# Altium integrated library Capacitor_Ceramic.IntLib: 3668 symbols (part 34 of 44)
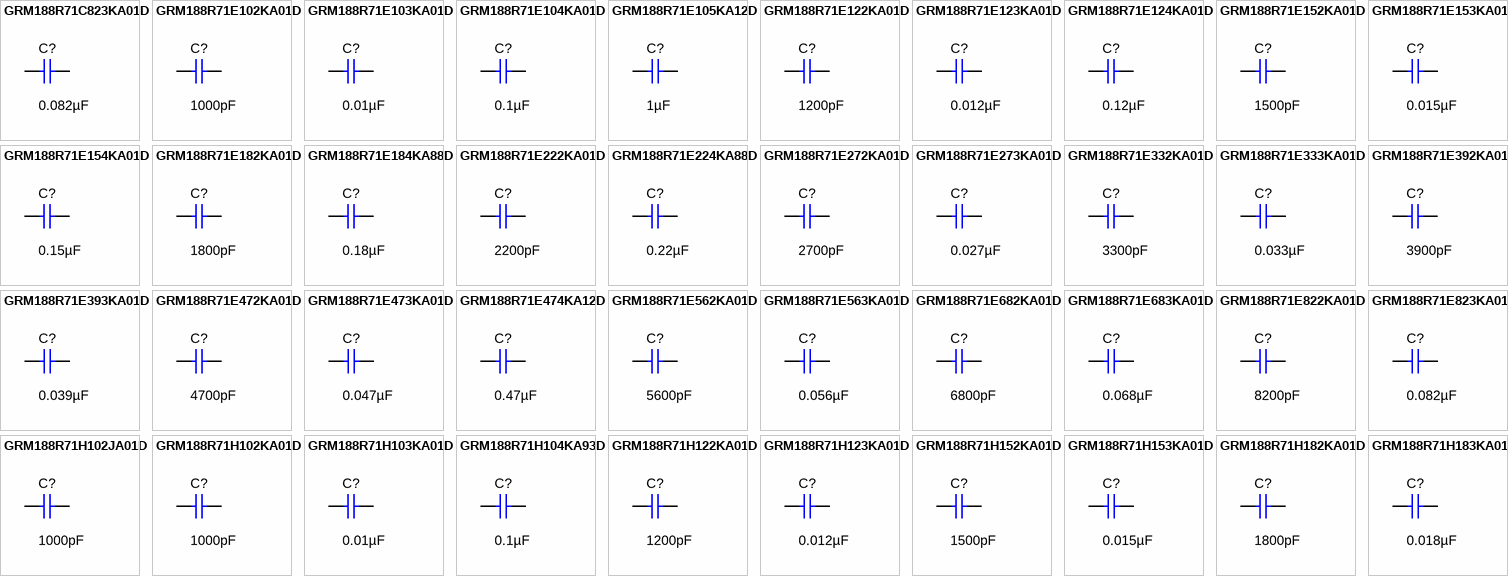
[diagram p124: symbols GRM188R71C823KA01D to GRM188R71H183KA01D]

## GRM188R71E123KA01D
designator C?  ValueDisplayed: 0.012µF  (hidden comment: GRM188R71E123KA01D)
CAP, CERM, 0.012 µF, 25 V,+/- 10%, X7R, 0603; Manufacturer: MuRata; Polarized: N; CompType: Capacitor; Value: 0.012uF; U/M: EA; Cap_F: 0.000000012; Tolerance_%: 10; VDC_V: 25; Value2: 25V; TaMin_C: -55; TaMax_C: 125; Cap_Case: 0603; SizeArea_mm2: 1.28; SizeAreaWB_mm2: 4.68; SizeX_mm: 1.6; SizeY_mm: 0.8; SizeZ_mm: 1; AEC Category: Q200
signal-integrity model Cap
simulation model Cap
footprint 0603
footprint 0603M
footprint 0603L
footprint 0603_HV
footprint 0603S
pins: 1, 2

## GRM188R71E124KA01D
designator C?  ValueDisplayed: 0.12µF  (hidden comment: GRM188R71E124KA01D)
CAP, CERM, 0.12 µF, 25 V,+/- 10%, X7R, 0603; Manufacturer: MuRata; Polarized: N; CompType: Capacitor; Value: 0.12uF; U/M: EA; Cap_F: 0.00000012; Tolerance_%: 10; VDC_V: 25; Value2: 25V; TaMin_C: -55; TaMax_C: 125; Cap_Case: 0603; SizeArea_mm2: 1.28; SizeAreaWB_mm2: 4.68; SizeX_mm: 1.6; SizeY_mm: 0.8; SizeZ_mm: 1; AEC Category: Q200
signal-integrity model Cap
simulation model Cap
footprint 0603
footprint 0603M
footprint 0603L
footprint 0603_HV
footprint 0603S
pins: 1, 2

## GRM188R71E152KA01D
designator C?  ValueDisplayed: 1500pF  (hidden comment: GRM188R71E152KA01D)
CAP, CERM, 1500 pF, 25 V,+/- 10%, X7R, 0603; Manufacturer: MuRata; Polarized: N; CompType: Capacitor; Value: 1500pF; U/M: EA; Cap_F: 0.0000000015; Tolerance_%: 10; VDC_V: 25; Value2: 25V; TaMin_C: -55; TaMax_C: 125; Cap_Case: 0603; SizeArea_mm2: 1.28; SizeAreaWB_mm2: 4.68; SizeX_mm: 1.6; SizeY_mm: 0.8; SizeZ_mm: 1; AEC Category: Q200; Green_Lifecycle: Active; Green_REACh: Passed
signal-integrity model Cap
simulation model Cap
footprint 0603
footprint 0603M
footprint 0603L
footprint 0603_HV
footprint 0603S
pins: 1, 2

## GRM188R71E153KA01D
designator C?  ValueDisplayed: 0.015µF  (hidden comment: GRM188R71E153KA01D)
CAP, CERM, 0.015 µF, 25 V,+/- 10%, X7R, 0603; Manufacturer: MuRata; Polarized: N; CompType: Capacitor; Value: 0.015uF; U/M: EA; Cap_F: 0.000000015; Tolerance_%: 10; VDC_V: 25; Value2: 25V; TaMin_C: -55; TaMax_C: 125; Cap_Case: 0603; SizeArea_mm2: 1.28; SizeAreaWB_mm2: 4.68; SizeX_mm: 1.6; SizeY_mm: 0.8; SizeZ_mm: 1; AEC Category: Q200; Green_Lifecycle: Active; Green_REACh: Passed
signal-integrity model Cap
simulation model Cap
footprint 0603
footprint 0603M
footprint 0603L
footprint 0603_HV
footprint 0603S
pins: 1, 2

## GRM188R71E154KA01D
designator C?  ValueDisplayed: 0.15µF  (hidden comment: GRM188R71E154KA01D)
CAP, CERM, 0.15 µF, 25 V,+/- 10%, X7R, 0603; Manufacturer: MuRata; Polarized: N; CompType: Capacitor; Value: 0.15uF; U/M: EA; Cap_F: 0.00000015; Tolerance_%: 10; VDC_V: 25; Value2: 25V; TaMin_C: -55; TaMax_C: 125; Cap_Case: 0603; SizeArea_mm2: 1.28; SizeAreaWB_mm2: 4.68; SizeX_mm: 1.6; SizeY_mm: 0.8; SizeZ_mm: 1; AEC Category: Q200; Green_Lifecycle: Active; Green_REACh: Passed
signal-integrity model Cap
simulation model Cap
footprint 0603
footprint 0603M
footprint 0603L
footprint 0603_HV
footprint 0603S
pins: 1, 2

## GRM188R71E182KA01D
designator C?  ValueDisplayed: 1800pF  (hidden comment: GRM188R71E182KA01D)
CAP, CERM, 1800 pF, 25 V,+/- 10%, X7R, 0603; Manufacturer: MuRata; Polarized: N; CompType: Capacitor; Value: 1800pF; U/M: EA; Cap_F: 0.0000000018; Tolerance_%: 10; VDC_V: 25; Value2: 25V; TaMin_C: -55; TaMax_C: 125; Cap_Case: 0603; SizeArea_mm2: 1.28; SizeAreaWB_mm2: 4.68; SizeX_mm: 1.6; SizeY_mm: 0.8; SizeZ_mm: 1; AEC Category: Q200; Green_Lifecycle: Active; Green_REACh: Passed
signal-integrity model Cap
simulation model Cap
footprint 0603
footprint 0603M
footprint 0603L
footprint 0603_HV
footprint 0603S
pins: 1, 2

## GRM188R71E184KA88D
designator C?  ValueDisplayed: 0.18µF  (hidden comment: GRM188R71E184KA88D)
CAP, CERM, 0.18 µF, 25 V,+/- 10%, X7R, 0603; Manufacturer: MuRata; Polarized: N; CompType: Capacitor; Value: 0.18uF; U/M: EA; Cap_F: 0.00000018; Tolerance_%: 10; VDC_V: 25; Value2: 25V; TaMin_C: -55; TaMax_C: 125; Cap_Case: 0603; SizeArea_mm2: 1.28; SizeAreaWB_mm2: 4.68; SizeX_mm: 1.6; SizeY_mm: 0.8; SizeZ_mm: 1; AEC Category: Q200; Green_Lifecycle: Active; Green_REACh: Passed
signal-integrity model Cap
simulation model Cap
footprint 0603
footprint 0603M
footprint 0603L
footprint 0603_HV
footprint 0603S
pins: 1, 2

## GRM188R71E222KA01D
designator C?  ValueDisplayed: 2200pF  (hidden comment: GRM188R71E222KA01D)
CAP, CERM, 2200 pF, 25 V,+/- 10%, X7R, 0603; Manufacturer: MuRata; Polarized: N; CompType: Capacitor; Value: 2200pF; U/M: EA; Cap_F: 0.0000000022; Tolerance_%: 10; VDC_V: 25; Value2: 25V; TaMin_C: -55; TaMax_C: 125; Cap_Case: 0603; SizeArea_mm2: 1.28; SizeAreaWB_mm2: 4.68; SizeX_mm: 1.6; SizeY_mm: 0.8; SizeZ_mm: 1; AEC Category: Q200; Green_Lifecycle: Active; Green_REACh: Passed
signal-integrity model Cap
simulation model Cap
footprint 0603
footprint 0603M
footprint 0603L
footprint 0603_HV
footprint 0603S
pins: 1, 2

## GRM188R71E224KA88D
designator C?  ValueDisplayed: 0.22µF  (hidden comment: GRM188R71E224KA88D)
CAP, CERM, 0.22 µF, 25 V,+/- 10%, X7R, 0603; Manufacturer: MuRata; Polarized: N; CompType: Capacitor; Value: 0.22uF; U/M: EA; Cap_F: 0.00000022; Tolerance_%: 10; VDC_V: 25; Value2: 25V; TaMin_C: -55; TaMax_C: 125; Cap_Case: 0603; SizeArea_mm2: 1.28; SizeAreaWB_mm2: 4.68; SizeX_mm: 1.6; SizeY_mm: 0.8; SizeZ_mm: 1; AEC Category: Q200; Green_Lifecycle: Active; Green_REACh: Passed
signal-integrity model Cap
simulation model Cap
footprint 0603
footprint 0603M
footprint 0603L
footprint 0603_HV
footprint 0603S
pins: 1, 2

## GRM188R71E272KA01D
designator C?  ValueDisplayed: 2700pF  (hidden comment: GRM188R71E272KA01D)
CAP, CERM, 2700 pF, 25 V,+/- 10%, X7R, 0603; Manufacturer: MuRata; Polarized: N; CompType: Capacitor; Value: 2700pF; U/M: EA; Cap_F: 0.0000000027; Tolerance_%: 10; VDC_V: 25; Value2: 25V; TaMin_C: -55; TaMax_C: 125; Cap_Case: 0603; SizeArea_mm2: 1.28; SizeAreaWB_mm2: 4.68; SizeX_mm: 1.6; SizeY_mm: 0.8; SizeZ_mm: 1; AEC Category: Q200; Green_Lifecycle: Active; Green_REACh: Passed
signal-integrity model Cap
simulation model Cap
footprint 0603
footprint 0603M
footprint 0603L
footprint 0603_HV
footprint 0603S
pins: 1, 2

## GRM188R71E273KA01D
designator C?  ValueDisplayed: 0.027µF  (hidden comment: GRM188R71E273KA01D)
CAP, CERM, 0.027 µF, 25 V,+/- 10%, X7R, 0603; Manufacturer: MuRata; Polarized: N; CompType: Capacitor; Value: 0.027uF; U/M: EA; Cap_F: 0.000000027; Tolerance_%: 10; VDC_V: 25; Value2: 25V; TaMin_C: -55; TaMax_C: 125; Cap_Case: 0603; SizeArea_mm2: 1.28; SizeAreaWB_mm2: 4.68; SizeX_mm: 1.6; SizeY_mm: 0.8; SizeZ_mm: 1; AEC Category: Q200
signal-integrity model Cap
simulation model Cap
footprint 0603
footprint 0603M
footprint 0603L
footprint 0603_HV
footprint 0603S
pins: 1, 2

## GRM188R71E332KA01D
designator C?  ValueDisplayed: 3300pF  (hidden comment: GRM188R71E332KA01D)
CAP, CERM, 3300 pF, 25 V,+/- 10%, X7R, 0603; Manufacturer: MuRata; Polarized: N; CompType: Capacitor; Value: 3300pF; U/M: EA; Cap_F: 0.0000000033; Tolerance_%: 10; VDC_V: 25; Value2: 25V; TaMin_C: -55; TaMax_C: 125; Cap_Case: 0603; SizeArea_mm2: 1.28; SizeAreaWB_mm2: 4.68; SizeX_mm: 1.6; SizeY_mm: 0.8; SizeZ_mm: 1; AEC Category: Q200; Green_Lifecycle: Active; Green_REACh: Passed
signal-integrity model Cap
simulation model Cap
footprint 0603
footprint 0603M
footprint 0603L
footprint 0603_HV
footprint 0603S
pins: 1, 2

## GRM188R71E333KA01D
designator C?  ValueDisplayed: 0.033µF  (hidden comment: GRM188R71E333KA01D)
CAP, CERM, 0.033 µF, 25 V,+/- 10%, X7R, 0603; Manufacturer: MuRata; Polarized: N; CompType: Capacitor; Value: 0.033uF; U/M: EA; Cap_F: 0.000000033; Tolerance_%: 10; VDC_V: 25; Value2: 25V; TaMin_C: -55; TaMax_C: 125; Cap_Case: 0603; SizeArea_mm2: 1.28; SizeAreaWB_mm2: 4.68; SizeX_mm: 1.6; SizeY_mm: 0.8; SizeZ_mm: 1; AEC Category: Q200; Green_Lifecycle: Active; Green_REACh: Passed
signal-integrity model Cap
simulation model Cap
footprint 0603
footprint 0603M
footprint 0603L
footprint 0603_HV
footprint 0603S
pins: 1, 2

## GRM188R71E392KA01D
designator C?  ValueDisplayed: 3900pF  (hidden comment: GRM188R71E392KA01D)
CAP, CERM, 3900 pF, 25 V,+/- 10%, X7R, 0603; Manufacturer: MuRata; Polarized: N; CompType: Capacitor; Value: 3900pF; U/M: EA; Cap_F: 0.0000000039; Tolerance_%: 10; VDC_V: 25; Value2: 25V; TaMin_C: -55; TaMax_C: 125; Cap_Case: 0603; SizeArea_mm2: 1.28; SizeAreaWB_mm2: 4.68; SizeX_mm: 1.6; SizeY_mm: 0.8; SizeZ_mm: 1; AEC Category: Q200; Green_Lifecycle: Active; Green_REACh: Passed
signal-integrity model Cap
simulation model Cap
footprint 0603
footprint 0603M
footprint 0603L
footprint 0603_HV
footprint 0603S
pins: 1, 2

## GRM188R71E393KA01D
designator C?  ValueDisplayed: 0.039µF  (hidden comment: GRM188R71E393KA01D)
CAP, CERM, 0.039 µF, 25 V,+/- 10%, X7R, 0603; Manufacturer: MuRata; Polarized: N; CompType: Capacitor; Value: 0.039uF; U/M: EA; Cap_F: 0.000000039; Tolerance_%: 10; VDC_V: 25; Value2: 25V; TaMin_C: -55; TaMax_C: 125; Cap_Case: 0603; SizeArea_mm2: 1.28; SizeAreaWB_mm2: 4.68; SizeX_mm: 1.6; SizeY_mm: 0.8; SizeZ_mm: 1; AEC Category: Q200
signal-integrity model Cap
simulation model Cap
footprint 0603
footprint 0603M
footprint 0603L
footprint 0603_HV
footprint 0603S
pins: 1, 2

## GRM188R71E472KA01D
designator C?  ValueDisplayed: 4700pF  (hidden comment: GRM188R71E472KA01D)
CAP, CERM, 4700 pF, 25 V,+/- 10%, X7R, 0603; Manufacturer: MuRata; Polarized: N; CompType: Capacitor; Value: 4700pF; U/M: EA; Cap_F: 0.0000000047; Tolerance_%: 10; VDC_V: 25; Value2: 25V; TaMin_C: -55; TaMax_C: 125; Cap_Case: 0603; SizeArea_mm2: 1.28; SizeAreaWB_mm2: 4.68; SizeX_mm: 1.6; SizeY_mm: 0.8; SizeZ_mm: 1; AEC Category: Q200
signal-integrity model Cap
simulation model Cap
footprint 0603
footprint 0603M
footprint 0603L
footprint 0603_HV
footprint 0603S
pins: 1, 2

## GRM188R71E473KA01D
designator C?  ValueDisplayed: 0.047µF  (hidden comment: GRM188R71E473KA01D)
CAP, CERM, 0.047 µF, 25 V,+/- 10%, X7R, 0603; Manufacturer: MuRata; Polarized: N; CompType: Capacitor; Value: 0.047uF; U/M: EA; Cap_F: 0.000000047; Tolerance_%: 10; VDC_V: 25; Value2: 25V; TaMin_C: -55; TaMax_C: 125; Cap_Case: 0603; SizeArea_mm2: 1.28; SizeAreaWB_mm2: 4.68; SizeX_mm: 1.6; SizeY_mm: 0.8; SizeZ_mm: 1; AEC Category: Q200; Green_Lifecycle: Active; Green_REACh: Passed
signal-integrity model Cap
simulation model Cap
footprint 0603
footprint 0603M
footprint 0603L
footprint 0603_HV
footprint 0603S
pins: 1, 2

## GRM188R71E474KA12D
designator C?  ValueDisplayed: 0.47µF  (hidden comment: GRM188R71E474KA12D)
CAP, CERM, 0.47 µF, 25 V,+/- 10%, X7R, 0603; Manufacturer: MuRata; Polarized: N; CompType: Capacitor; Value: 0.47uF; U/M: EA; Cap_F: 0.00000047; Tolerance_%: 10; VDC_V: 25; Value2: 25V; TaMin_C: -55; TaMax_C: 125; Cap_Case: 0603; SizeArea_mm2: 1.28; SizeAreaWB_mm2: 4.68; SizeX_mm: 1.6; SizeY_mm: 0.8; SizeZ_mm: 1; AEC Category: Q200; Green_Lifecycle: Active; Green_REACh: Passed
signal-integrity model Cap
simulation model Cap
footprint 0603
footprint 0603M
footprint 0603L
footprint 0603_HV
footprint 0603S
pins: 1, 2

## GRM188R71E562KA01D
designator C?  ValueDisplayed: 5600pF  (hidden comment: GRM188R71E562KA01D)
CAP, CERM, 5600 pF, 25 V,+/- 10%, X7R, 0603; Manufacturer: MuRata; Polarized: N; CompType: Capacitor; Value: 5600pF; U/M: EA; Cap_F: 0.0000000056; Tolerance_%: 10; VDC_V: 25; Value2: 25V; TaMin_C: -55; TaMax_C: 125; Cap_Case: 0603; SizeArea_mm2: 1.28; SizeAreaWB_mm2: 4.68; SizeX_mm: 1.6; SizeY_mm: 0.8; SizeZ_mm: 1; AEC Category: Q200
signal-integrity model Cap
simulation model Cap
footprint 0603
footprint 0603M
footprint 0603L
footprint 0603_HV
footprint 0603S
pins: 1, 2

## GRM188R71E563KA01D
designator C?  ValueDisplayed: 0.056µF  (hidden comment: GRM188R71E563KA01D)
CAP, CERM, 0.056 µF, 25 V,+/- 10%, X7R, 0603; Manufacturer: MuRata; Polarized: N; CompType: Capacitor; Value: 0.056uF; U/M: EA; Cap_F: 0.000000056; Tolerance_%: 10; VDC_V: 25; Value2: 25V; TaMin_C: -55; TaMax_C: 125; Cap_Case: 0603; SizeArea_mm2: 1.28; SizeAreaWB_mm2: 4.68; SizeX_mm: 1.6; SizeY_mm: 0.8; SizeZ_mm: 1; AEC Category: Q200; Green_Lifecycle: Active; Green_REACh: Passed
signal-integrity model Cap
simulation model Cap
footprint 0603
footprint 0603M
footprint 0603L
footprint 0603_HV
footprint 0603S
pins: 1, 2

## GRM188R71E682KA01D
designator C?  ValueDisplayed: 6800pF  (hidden comment: GRM188R71E682KA01D)
CAP, CERM, 6800 pF, 25 V,+/- 10%, X7R, 0603; Manufacturer: MuRata; Polarized: N; CompType: Capacitor; Value: 6800pF; U/M: EA; Cap_F: 0.0000000068; Tolerance_%: 10; VDC_V: 25; Value2: 25V; TaMin_C: -55; TaMax_C: 125; Cap_Case: 0603; SizeArea_mm2: 1.28; SizeAreaWB_mm2: 4.68; SizeX_mm: 1.6; SizeY_mm: 0.8; SizeZ_mm: 1; AEC Category: Q200
signal-integrity model Cap
simulation model Cap
footprint 0603
footprint 0603M
footprint 0603L
footprint 0603_HV
footprint 0603S
pins: 1, 2

## GRM188R71E683KA01D
designator C?  ValueDisplayed: 0.068µF  (hidden comment: GRM188R71E683KA01D)
CAP, CERM, 0.068 µF, 25 V,+/- 10%, X7R, 0603; Manufacturer: MuRata; Polarized: N; CompType: Capacitor; Value: 0.068uF; U/M: EA; Cap_F: 0.000000068; Tolerance_%: 10; VDC_V: 25; Value2: 25V; TaMin_C: -55; TaMax_C: 125; Cap_Case: 0603; SizeArea_mm2: 1.28; SizeAreaWB_mm2: 4.68; SizeX_mm: 1.6; SizeY_mm: 0.8; SizeZ_mm: 1; AEC Category: Q200; Green_Lifecycle: Active; Green_REACh: Passed
signal-integrity model Cap
simulation model Cap
footprint 0603
footprint 0603M
footprint 0603L
footprint 0603_HV
footprint 0603S
pins: 1, 2

## GRM188R71E822KA01D
designator C?  ValueDisplayed: 8200pF  (hidden comment: GRM188R71E822KA01D)
CAP, CERM, 8200 pF, 25 V,+/- 10%, X7R, 0603; Manufacturer: MuRata; Polarized: N; CompType: Capacitor; Value: 8200pF; U/M: EA; Cap_F: 0.0000000082; Tolerance_%: 10; VDC_V: 25; Value2: 25V; TaMin_C: -55; TaMax_C: 125; Cap_Case: 0603; SizeArea_mm2: 1.28; SizeAreaWB_mm2: 4.68; SizeX_mm: 1.6; SizeY_mm: 0.8; SizeZ_mm: 1; AEC Category: Q200; Green_Lifecycle: Active; Green_REACh: Passed
signal-integrity model Cap
simulation model Cap
footprint 0603
footprint 0603M
footprint 0603L
footprint 0603_HV
footprint 0603S
pins: 1, 2

## GRM188R71E823KA01D
designator C?  ValueDisplayed: 0.082µF  (hidden comment: GRM188R71E823KA01D)
CAP, CERM, 0.082 µF, 25 V,+/- 10%, X7R, 0603; Manufacturer: MuRata; Polarized: N; CompType: Capacitor; Value: 0.082uF; U/M: EA; Cap_F: 0.000000082; Tolerance_%: 10; VDC_V: 25; Value2: 25V; TaMin_C: -55; TaMax_C: 125; Cap_Case: 0603; SizeArea_mm2: 1.28; SizeAreaWB_mm2: 4.68; SizeX_mm: 1.6; SizeY_mm: 0.8; SizeZ_mm: 1; AEC Category: Q200; Green_Lifecycle: Active; Green_REACh: Passed
signal-integrity model Cap
simulation model Cap
footprint 0603
footprint 0603M
footprint 0603L
footprint 0603_HV
footprint 0603S
pins: 1, 2

## GRM188R71H102JA01D
designator C?  ValueDisplayed: 1000pF  (hidden comment: GRM188R71H102JA01D)
CAP, CERM, 1000 pF, 50 V,+/- 5%, X7R, 0603; Manufacturer: MuRata; Polarized: N; CompType: Capacitor; Value: 1000pF; U/M: EA; Cap_F: 0.000000001; Tolerance_%: 5; VDC_V: 50; Value2: 50V; TaMin_C: -55; TaMax_C: 125; Cap_Case: 0603; SizeArea_mm2: 1.28; SizeAreaWB_mm2: 4.68; SizeX_mm: 1.6; SizeY_mm: 0.8; SizeZ_mm: 1; AEC Category: Q200
signal-integrity model Cap
simulation model Cap
footprint 0603
footprint 0603M
footprint 0603L
footprint 0603_HV
footprint 0603S
pins: 1, 2

## GRM188R71H102KA01D
designator C?  ValueDisplayed: 1000pF  (hidden comment: GRM188R71H102KA01D)
CAP, CERM, 1000 pF, 50 V,+/- 10%, X7R, 0603; Manufacturer: MuRata; Polarized: N; CompType: Capacitor; Value: 1000pF; U/M: EA; Cap_F: 0.000000001; Tolerance_%: 10; VDC_V: 50; Value2: 50V; TaMin_C: -55; TaMax_C: 125; Cap_Case: 0603; SizeArea_mm2: 1.28; SizeAreaWB_mm2: 4.68; SizeX_mm: 1.6; SizeY_mm: 0.8; SizeZ_mm: 1; AEC Category: Q200; Green_Lifecycle: Active; Green_REACh: Passed
signal-integrity model Cap
simulation model Cap
footprint 0603
footprint 0603M
footprint 0603L
footprint 0603_HV
footprint 0603S
pins: 1, 2

## GRM188R71H103KA01D
designator C?  ValueDisplayed: 0.01µF  (hidden comment: GRM188R71H103KA01D)
CAP, CERM, 0.01 µF, 50 V,+/- 10%, X7R, 0603; Manufacturer: MuRata; Polarized: N; CompType: Capacitor; Value: 0.01uF; U/M: EA; Cap_F: 0.00000001; Tolerance_%: 10; VDC_V: 50; Value2: 50V; TaMin_C: -55; TaMax_C: 125; Cap_Case: 0603; SizeArea_mm2: 1.28; SizeAreaWB_mm2: 4.68; SizeX_mm: 1.6; SizeY_mm: 0.8; SizeZ_mm: 1; AEC Category: Q200; Green_Lifecycle: Active; Green_REACh: Passed
signal-integrity model Cap
simulation model Cap
footprint 0603
footprint 0603M
footprint 0603L
footprint 0603_HV
footprint 0603S
pins: 1, 2

## GRM188R71H104KA93D
designator C?  ValueDisplayed: 0.1µF  (hidden comment: GRM188R71H104KA93D)
CAP, CERM, 0.1 µF, 50 V,+/- 10%, X7R, 0603; Manufacturer: MuRata; Polarized: N; CompType: Capacitor; Value: 0.1uF; U/M: EA; Cap_F: 0.0000001; Tolerance_%: 10; VDC_V: 50; Value2: 50V; TaMin_C: -55; TaMax_C: 125; Cap_Case: 0603; SizeArea_mm2: 1.28; SizeAreaWB_mm2: 4.68; SizeX_mm: 1.6; SizeY_mm: 0.8; SizeZ_mm: 1; AEC Category: Q200; Green_Lifecycle: Active; Green_REACh: Passed
signal-integrity model Cap
simulation model Cap
footprint 0603
footprint 0603M
footprint 0603L
footprint 0603_HV
footprint 0603S
pins: 1, 2

## GRM188R71H122KA01D
designator C?  ValueDisplayed: 1200pF  (hidden comment: GRM188R71H122KA01D)
CAP, CERM, 1200 pF, 50 V,+/- 10%, X7R, 0603; Manufacturer: MuRata; Polarized: N; CompType: Capacitor; Value: 1200pF; U/M: EA; Cap_F: 0.0000000012; Tolerance_%: 10; VDC_V: 50; Value2: 50V; TaMin_C: -55; TaMax_C: 125; Cap_Case: 0603; SizeArea_mm2: 1.28; SizeAreaWB_mm2: 4.68; SizeX_mm: 1.6; SizeY_mm: 0.8; SizeZ_mm: 1; AEC Category: Q200; Green_Lifecycle: Active; Green_REACh: Passed
signal-integrity model Cap
simulation model Cap
footprint 0603
footprint 0603M
footprint 0603L
footprint 0603_HV
footprint 0603S
pins: 1, 2

## GRM188R71H123KA01D
designator C?  ValueDisplayed: 0.012µF  (hidden comment: GRM188R71H123KA01D)
CAP, CERM, 0.012 µF, 50 V,+/- 10%, X7R, 0603; Manufacturer: MuRata; Polarized: N; CompType: Capacitor; Value: 0.012uF; U/M: EA; Cap_F: 0.000000012; Tolerance_%: 10; VDC_V: 50; Value2: 50V; TaMin_C: -55; TaMax_C: 125; Cap_Case: 0603; SizeArea_mm2: 1.28; SizeAreaWB_mm2: 4.68; SizeX_mm: 1.6; SizeY_mm: 0.8; SizeZ_mm: 1; AEC Category: Q200; Green_Lifecycle: Active; Green_REACh: Passed
signal-integrity model Cap
simulation model Cap
footprint 0603
footprint 0603M
footprint 0603L
footprint 0603_HV
footprint 0603S
pins: 1, 2

## GRM188R71H152KA01D
designator C?  ValueDisplayed: 1500pF  (hidden comment: GRM188R71H152KA01D)
CAP, CERM, 1500 pF, 50 V,+/- 10%, X7R, 0603; Manufacturer: MuRata; Polarized: N; CompType: Capacitor; Value: 1500pF; U/M: EA; Cap_F: 0.0000000015; Tolerance_%: 10; VDC_V: 50; Value2: 50V; TaMin_C: -55; TaMax_C: 125; Cap_Case: 0603; SizeArea_mm2: 1.28; SizeAreaWB_mm2: 4.68; SizeX_mm: 1.6; SizeY_mm: 0.8; SizeZ_mm: 1; AEC Category: Q200; Green_Lifecycle: Active; Green_REACh: Passed
signal-integrity model Cap
simulation model Cap
footprint 0603
footprint 0603M
footprint 0603L
footprint 0603_HV
footprint 0603S
pins: 1, 2

## GRM188R71H153KA01D
designator C?  ValueDisplayed: 0.015µF  (hidden comment: GRM188R71H153KA01D)
CAP, CERM, 0.015 µF, 50 V,+/- 10%, X7R, 0603; Manufacturer: MuRata; Polarized: N; CompType: Capacitor; Value: 0.015uF; U/M: EA; Cap_F: 0.000000015; Tolerance_%: 10; VDC_V: 50; Value2: 50V; TaMin_C: -55; TaMax_C: 125; Cap_Case: 0603; SizeArea_mm2: 1.28; SizeAreaWB_mm2: 4.68; SizeX_mm: 1.6; SizeY_mm: 0.8; SizeZ_mm: 1; AEC Category: Q200; Green_Lifecycle: Active; Green_REACh: Passed
signal-integrity model Cap
simulation model Cap
footprint 0603
footprint 0603M
footprint 0603L
footprint 0603_HV
footprint 0603S
pins: 1, 2

## GRM188R71H182KA01D
designator C?  ValueDisplayed: 1800pF  (hidden comment: GRM188R71H182KA01D)
CAP, CERM, 1800 pF, 50 V,+/- 10%, X7R, 0603; Manufacturer: MuRata; Polarized: N; CompType: Capacitor; Value: 1800pF; U/M: EA; Cap_F: 0.0000000018; Tolerance_%: 10; VDC_V: 50; Value2: 50V; TaMin_C: -55; TaMax_C: 125; Cap_Case: 0603; SizeArea_mm2: 1.28; SizeAreaWB_mm2: 4.68; SizeX_mm: 1.6; SizeY_mm: 0.8; SizeZ_mm: 1; AEC Category: Q200; Green_Lifecycle: Active; Green_REACh: Passed
signal-integrity model Cap
simulation model Cap
footprint 0603
footprint 0603M
footprint 0603L
footprint 0603_HV
footprint 0603S
pins: 1, 2

## GRM188R71H183KA01D
designator C?  ValueDisplayed: 0.018µF  (hidden comment: GRM188R71H183KA01D)
CAP, CERM, 0.018 µF, 50 V,+/- 10%, X7R, 0603; Manufacturer: MuRata; Polarized: N; CompType: Capacitor; Value: 0.018uF; U/M: EA; Cap_F: 0.000000018; Tolerance_%: 10; VDC_V: 50; Value2: 50V; TaMin_C: -55; TaMax_C: 125; Cap_Case: 0603; SizeArea_mm2: 1.28; SizeAreaWB_mm2: 4.68; SizeX_mm: 1.6; SizeY_mm: 0.8; SizeZ_mm: 1; AEC Category: Q200
signal-integrity model Cap
simulation model Cap
footprint 0603
footprint 0603M
footprint 0603L
footprint 0603_HV
footprint 0603S
pins: 1, 2

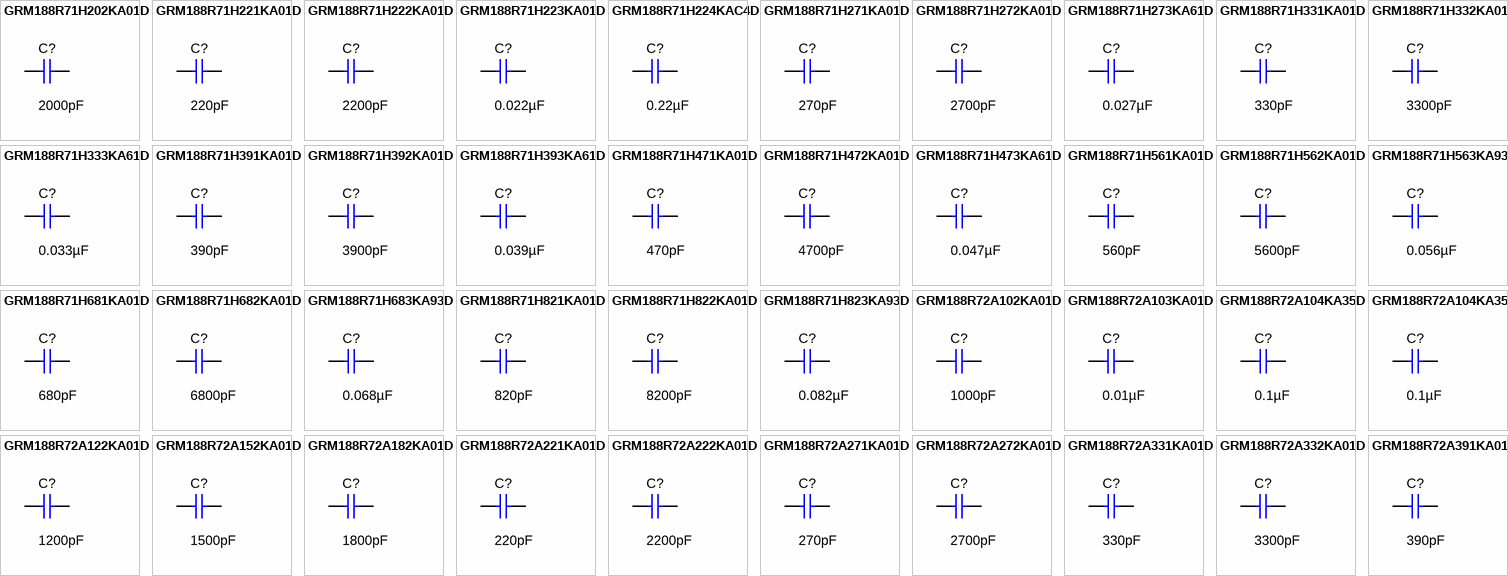
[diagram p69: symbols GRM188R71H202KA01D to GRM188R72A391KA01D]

## GRM188R71H202KA01D
designator C?  ValueDisplayed: 2000pF  (hidden comment: GRM188R71H202KA01D)
CAP, CERM, 2000 pF, 50 V,+/- 10%, X7R, 0603; Manufacturer: MuRata; Polarized: N; CompType: Capacitor; Value: 2000pF; U/M: EA; Cap_F: 0.000000002; Tolerance_%: 10; VDC_V: 50; Value2: 50V; TaMin_C: -55; TaMax_C: 125; Cap_Case: 0603; SizeArea_mm2: 1.28; SizeAreaWB_mm2: 4.68; SizeX_mm: 1.6; SizeY_mm: 0.8; SizeZ_mm: 1; AEC Category: Q200
signal-integrity model Cap
simulation model Cap
footprint 0603
footprint 0603M
footprint 0603L
footprint 0603_HV
footprint 0603S
pins: 1, 2

## GRM188R71H221KA01D
designator C?  ValueDisplayed: 220pF  (hidden comment: GRM188R71H221KA01D)
CAP, CERM, 220 pF, 50 V,+/- 10%, X7R, 0603; Manufacturer: MuRata; Polarized: N; CompType: Capacitor; Value: 220pF; U/M: EA; Cap_F: 0.00000000022; Tolerance_%: 10; VDC_V: 50; Value2: 50V; TaMin_C: -55; TaMax_C: 125; Cap_Case: 0603; SizeArea_mm2: 1.28; SizeAreaWB_mm2: 4.68; SizeX_mm: 1.6; SizeY_mm: 0.8; SizeZ_mm: 1; AEC Category: Q200; Green_Lifecycle: Active; Green_REACh: Passed
signal-integrity model Cap
simulation model Cap
footprint 0603
footprint 0603M
footprint 0603L
footprint 0603_HV
footprint 0603S
pins: 1, 2

## GRM188R71H222KA01D
designator C?  ValueDisplayed: 2200pF  (hidden comment: GRM188R71H222KA01D)
CAP, CERM, 2200 pF, 50 V,+/- 10%, X7R, 0603; Manufacturer: MuRata; Polarized: N; CompType: Capacitor; Value: 2200pF; U/M: EA; Cap_F: 0.0000000022; Tolerance_%: 10; VDC_V: 50; Value2: 50V; TaMin_C: -55; TaMax_C: 125; Cap_Case: 0603; SizeArea_mm2: 1.28; SizeAreaWB_mm2: 4.68; SizeX_mm: 1.6; SizeY_mm: 0.8; SizeZ_mm: 1; AEC Category: Q200; Green_Lifecycle: Active; Green_REACh: Passed
signal-integrity model Cap
simulation model Cap
footprint 0603
footprint 0603M
footprint 0603L
footprint 0603_HV
footprint 0603S
pins: 1, 2

## GRM188R71H223KA01D
designator C?  ValueDisplayed: 0.022µF  (hidden comment: GRM188R71H223KA01D)
CAP, CERM, 0.022 µF, 50 V,+/- 10%, X7R, 0603; Manufacturer: MuRata; Polarized: N; CompType: Capacitor; Value: 0.022uF; U/M: EA; Cap_F: 0.000000022; Tolerance_%: 10; VDC_V: 50; Value2: 50V; TaMin_C: -55; TaMax_C: 125; Cap_Case: 0603; SizeArea_mm2: 1.28; SizeAreaWB_mm2: 4.68; SizeX_mm: 1.6; SizeY_mm: 0.8; SizeZ_mm: 1; AEC Category: Q200; Green_Lifecycle: Active; Green_REACh: Passed
signal-integrity model Cap
simulation model Cap
footprint 0603
footprint 0603M
footprint 0603L
footprint 0603_HV
footprint 0603S
pins: 1, 2

## GRM188R71H224KAC4D
designator C?  ValueDisplayed: 0.22µF  (hidden comment: GRM188R71H224KAC4D)
CAP, CERM, 0.22 µF, 50 V,+/- 10%, X7R, 0603; Manufacturer: MuRata; Polarized: N; CompType: Capacitor; Value: 0.22uF; U/M: EA; Cap_F: 0.00000022; Tolerance_%: 10; VDC_V: 50; Value2: 50V; TaMin_C: -55; TaMax_C: 125; Cap_Case: 0603; SizeArea_mm2: 1.28; SizeAreaWB_mm2: 4.68; SizeX_mm: 1.6; SizeY_mm: 0.8; SizeZ_mm: 1; AEC Category: Q200
signal-integrity model Cap
simulation model Cap
footprint 0603
footprint 0603M
footprint 0603L
footprint 0603_HV
footprint 0603S
pins: 1, 2

## GRM188R71H271KA01D
designator C?  ValueDisplayed: 270pF  (hidden comment: GRM188R71H271KA01D)
CAP, CERM, 270 pF, 50 V,+/- 10%, X7R, 0603; Manufacturer: MuRata; Polarized: N; CompType: Capacitor; Value: 270pF; U/M: EA; Cap_F: 0.00000000027; Tolerance_%: 10; VDC_V: 50; Value2: 50V; TaMin_C: -55; TaMax_C: 125; Cap_Case: 0603; SizeArea_mm2: 1.28; SizeAreaWB_mm2: 4.68; SizeX_mm: 1.6; SizeY_mm: 0.8; SizeZ_mm: 1; AEC Category: Q200
signal-integrity model Cap
simulation model Cap
footprint 0603
footprint 0603M
footprint 0603L
footprint 0603_HV
footprint 0603S
pins: 1, 2

## GRM188R71H272KA01D
designator C?  ValueDisplayed: 2700pF  (hidden comment: GRM188R71H272KA01D)
CAP, CERM, 2700 pF, 50 V,+/- 10%, X7R, 0603; Manufacturer: MuRata; Polarized: N; CompType: Capacitor; Value: 2700pF; U/M: EA; Cap_F: 0.0000000027; Tolerance_%: 10; VDC_V: 50; Value2: 50V; TaMin_C: -55; TaMax_C: 125; Cap_Case: 0603; SizeArea_mm2: 1.28; SizeAreaWB_mm2: 4.68; SizeX_mm: 1.6; SizeY_mm: 0.8; SizeZ_mm: 1; AEC Category: Q200; Green_Lifecycle: Active; Green_REACh: Passed
signal-integrity model Cap
simulation model Cap
footprint 0603
footprint 0603M
footprint 0603L
footprint 0603_HV
footprint 0603S
pins: 1, 2

## GRM188R71H273KA61D
designator C?  ValueDisplayed: 0.027µF  (hidden comment: GRM188R71H273KA61D)
CAP, CERM, 0.027 µF, 50 V,+/- 10%, X7R, 0603; Manufacturer: MuRata; Polarized: N; CompType: Capacitor; Value: 0.027uF; U/M: EA; Cap_F: 0.000000027; Tolerance_%: 10; VDC_V: 50; Value2: 50V; TaMin_C: -55; TaMax_C: 125; Cap_Case: 0603; SizeArea_mm2: 1.28; SizeAreaWB_mm2: 4.68; SizeX_mm: 1.6; SizeY_mm: 0.8; SizeZ_mm: 1; AEC Category: Q200
signal-integrity model Cap
simulation model Cap
footprint 0603
footprint 0603M
footprint 0603L
footprint 0603_HV
footprint 0603S
pins: 1, 2

## GRM188R71H331KA01D
designator C?  ValueDisplayed: 330pF  (hidden comment: GRM188R71H331KA01D)
CAP, CERM, 330 pF, 50 V,+/- 10%, X7R, 0603; Manufacturer: MuRata; Polarized: N; CompType: Capacitor; Value: 330pF; U/M: EA; Cap_F: 0.00000000033; Tolerance_%: 10; VDC_V: 50; Value2: 50V; TaMin_C: -55; TaMax_C: 125; Cap_Case: 0603; SizeArea_mm2: 1.28; SizeAreaWB_mm2: 4.68; SizeX_mm: 1.6; SizeY_mm: 0.8; SizeZ_mm: 1; AEC Category: Q200; Green_Lifecycle: Active; Green_REACh: Passed
signal-integrity model Cap
simulation model Cap
footprint 0603
footprint 0603M
footprint 0603L
footprint 0603_HV
footprint 0603S
pins: 1, 2

## GRM188R71H332KA01D
designator C?  ValueDisplayed: 3300pF  (hidden comment: GRM188R71H332KA01D)
CAP, CERM, 3300 pF, 50 V,+/- 10%, X7R, 0603; Manufacturer: MuRata; Polarized: N; CompType: Capacitor; Value: 3300pF; U/M: EA; Cap_F: 0.0000000033; Tolerance_%: 10; VDC_V: 50; Value2: 50V; TaMin_C: -55; TaMax_C: 125; Cap_Case: 0603; SizeArea_mm2: 1.28; SizeAreaWB_mm2: 4.68; SizeX_mm: 1.6; SizeY_mm: 0.8; SizeZ_mm: 1; AEC Category: Q200; Green_Lifecycle: Active; Green_REACh: Passed
signal-integrity model Cap
simulation model Cap
footprint 0603
footprint 0603M
footprint 0603L
footprint 0603_HV
footprint 0603S
pins: 1, 2

## GRM188R71H333KA61D
designator C?  ValueDisplayed: 0.033µF  (hidden comment: GRM188R71H333KA61D)
CAP, CERM, 0.033 µF, 50 V,+/- 10%, X7R, 0603; Manufacturer: MuRata; Polarized: N; CompType: Capacitor; Value: 0.033uF; U/M: EA; Cap_F: 0.000000033; Tolerance_%: 10; VDC_V: 50; Value2: 50V; TaMin_C: -55; TaMax_C: 125; Cap_Case: 0603; SizeArea_mm2: 1.28; SizeAreaWB_mm2: 4.68; SizeX_mm: 1.6; SizeY_mm: 0.8; SizeZ_mm: 1; AEC Category: Q200; Green_Lifecycle: Active; Green_REACh: Passed
signal-integrity model Cap
simulation model Cap
footprint 0603
footprint 0603M
footprint 0603L
footprint 0603_HV
footprint 0603S
pins: 1, 2

## GRM188R71H391KA01D
designator C?  ValueDisplayed: 390pF  (hidden comment: GRM188R71H391KA01D)
CAP, CERM, 390 pF, 50 V,+/- 10%, X7R, 0603; Manufacturer: MuRata; Polarized: N; CompType: Capacitor; Value: 390pF; U/M: EA; Cap_F: 0.00000000039; Tolerance_%: 10; VDC_V: 50; Value2: 50V; TaMin_C: -55; TaMax_C: 125; Cap_Case: 0603; SizeArea_mm2: 1.28; SizeAreaWB_mm2: 4.68; SizeX_mm: 1.6; SizeY_mm: 0.8; SizeZ_mm: 1; AEC Category: Q200
signal-integrity model Cap
simulation model Cap
footprint 0603
footprint 0603M
footprint 0603L
footprint 0603_HV
footprint 0603S
pins: 1, 2

## GRM188R71H392KA01D
designator C?  ValueDisplayed: 3900pF  (hidden comment: GRM188R71H392KA01D)
CAP, CERM, 3900 pF, 50 V,+/- 10%, X7R, 0603; Manufacturer: MuRata; Polarized: N; CompType: Capacitor; Value: 3900pF; U/M: EA; Cap_F: 0.0000000039; Tolerance_%: 10; VDC_V: 50; Value2: 50V; TaMin_C: -55; TaMax_C: 125; Cap_Case: 0603; SizeArea_mm2: 1.28; SizeAreaWB_mm2: 4.68; SizeX_mm: 1.6; SizeY_mm: 0.8; SizeZ_mm: 1; AEC Category: Q200; Green_Lifecycle: Active; Green_REACh: Passed
signal-integrity model Cap
simulation model Cap
footprint 0603
footprint 0603M
footprint 0603L
footprint 0603_HV
footprint 0603S
pins: 1, 2

## GRM188R71H393KA61D
designator C?  ValueDisplayed: 0.039µF  (hidden comment: GRM188R71H393KA61D)
CAP, CERM, 0.039 µF, 50 V,+/- 10%, X7R, 0603; Manufacturer: MuRata; Polarized: N; CompType: Capacitor; Value: 0.039uF; U/M: EA; Cap_F: 0.000000039; Tolerance_%: 10; VDC_V: 50; Value2: 50V; TaMin_C: -55; TaMax_C: 125; Cap_Case: 0603; SizeArea_mm2: 1.28; SizeAreaWB_mm2: 4.68; SizeX_mm: 1.6; SizeY_mm: 0.8; SizeZ_mm: 1; AEC Category: Q200
signal-integrity model Cap
simulation model Cap
footprint 0603
footprint 0603M
footprint 0603L
footprint 0603_HV
footprint 0603S
pins: 1, 2

## GRM188R71H471KA01D
designator C?  ValueDisplayed: 470pF  (hidden comment: GRM188R71H471KA01D)
CAP, CERM, 470 pF, 50 V,+/- 10%, X7R, 0603; Manufacturer: MuRata; Polarized: N; CompType: Capacitor; Value: 470pF; U/M: EA; Cap_F: 0.00000000047; Tolerance_%: 10; VDC_V: 50; Value2: 50V; TaMin_C: -55; TaMax_C: 125; Cap_Case: 0603; SizeArea_mm2: 1.28; SizeAreaWB_mm2: 4.68; SizeX_mm: 1.6; SizeY_mm: 0.8; SizeZ_mm: 1; AEC Category: Q200; Green_Lifecycle: Active; Green_REACh: Passed
signal-integrity model Cap
simulation model Cap
footprint 0603
footprint 0603M
footprint 0603L
footprint 0603_HV
footprint 0603S
pins: 1, 2

## GRM188R71H472KA01D
designator C?  ValueDisplayed: 4700pF  (hidden comment: GRM188R71H472KA01D)
CAP, CERM, 4700 pF, 50 V,+/- 10%, X7R, 0603; Manufacturer: MuRata; Polarized: N; CompType: Capacitor; Value: 4700pF; U/M: EA; Cap_F: 0.0000000047; Tolerance_%: 10; VDC_V: 50; Value2: 50V; TaMin_C: -55; TaMax_C: 125; Cap_Case: 0603; SizeArea_mm2: 1.28; SizeAreaWB_mm2: 4.68; SizeX_mm: 1.6; SizeY_mm: 0.8; SizeZ_mm: 1; AEC Category: Q200; Green_Lifecycle: Active; Green_REACh: Passed
signal-integrity model Cap
simulation model Cap
footprint 0603
footprint 0603M
footprint 0603L
footprint 0603_HV
footprint 0603S
pins: 1, 2

## GRM188R71H473KA61D
designator C?  ValueDisplayed: 0.047µF  (hidden comment: GRM188R71H473KA61D)
CAP, CERM, 0.047 µF, 50 V,+/- 10%, X7R, 0603; Manufacturer: MuRata; Polarized: N; CompType: Capacitor; Value: 0.047uF; U/M: EA; Cap_F: 0.000000047; Tolerance_%: 10; VDC_V: 50; Value2: 50V; TaMin_C: -55; TaMax_C: 125; Cap_Case: 0603; SizeArea_mm2: 1.28; SizeAreaWB_mm2: 4.68; SizeX_mm: 1.6; SizeY_mm: 0.8; SizeZ_mm: 1; AEC Category: Q200; Green_Lifecycle: Active; Green_REACh: Passed
signal-integrity model Cap
simulation model Cap
footprint 0603
footprint 0603M
footprint 0603L
footprint 0603_HV
footprint 0603S
pins: 1, 2

## GRM188R71H561KA01D
designator C?  ValueDisplayed: 560pF  (hidden comment: GRM188R71H561KA01D)
CAP, CERM, 560 pF, 50 V,+/- 10%, X7R, 0603; Manufacturer: MuRata; Polarized: N; CompType: Capacitor; Value: 560pF; U/M: EA; Cap_F: 0.00000000056; Tolerance_%: 10; VDC_V: 50; Value2: 50V; TaMin_C: -55; TaMax_C: 125; Cap_Case: 0603; SizeArea_mm2: 1.28; SizeAreaWB_mm2: 4.68; SizeX_mm: 1.6; SizeY_mm: 0.8; SizeZ_mm: 1; AEC Category: Q200
signal-integrity model Cap
simulation model Cap
footprint 0603
footprint 0603M
footprint 0603L
footprint 0603_HV
footprint 0603S
pins: 1, 2

## GRM188R71H562KA01D
designator C?  ValueDisplayed: 5600pF  (hidden comment: GRM188R71H562KA01D)
CAP, CERM, 5600 pF, 50 V,+/- 10%, X7R, 0603; Manufacturer: MuRata; Polarized: N; CompType: Capacitor; Value: 5600pF; U/M: EA; Cap_F: 0.0000000056; Tolerance_%: 10; VDC_V: 50; Value2: 50V; TaMin_C: -55; TaMax_C: 125; Cap_Case: 0603; SizeArea_mm2: 1.28; SizeAreaWB_mm2: 4.68; SizeX_mm: 1.6; SizeY_mm: 0.8; SizeZ_mm: 1; AEC Category: Q200; Green_Lifecycle: Active; Green_REACh: Passed
signal-integrity model Cap
simulation model Cap
footprint 0603
footprint 0603M
footprint 0603L
footprint 0603_HV
footprint 0603S
pins: 1, 2

## GRM188R71H563KA93D
designator C?  ValueDisplayed: 0.056µF  (hidden comment: GRM188R71H563KA93D)
CAP, CERM, 0.056 µF, 50 V,+/- 10%, X7R, 0603; Manufacturer: MuRata; Polarized: N; CompType: Capacitor; Value: 0.056uF; U/M: EA; Cap_F: 0.000000056; Tolerance_%: 10; VDC_V: 50; Value2: 50V; TaMin_C: -55; TaMax_C: 125; Cap_Case: 0603; SizeArea_mm2: 1.28; SizeAreaWB_mm2: 4.68; SizeX_mm: 1.6; SizeY_mm: 0.8; SizeZ_mm: 1; AEC Category: Q200; Green_Lifecycle: Active; Green_REACh: Passed
signal-integrity model Cap
simulation model Cap
footprint 0603
footprint 0603M
footprint 0603L
footprint 0603_HV
footprint 0603S
pins: 1, 2

## GRM188R71H681KA01D
designator C?  ValueDisplayed: 680pF  (hidden comment: GRM188R71H681KA01D)
CAP, CERM, 680 pF, 50 V,+/- 10%, X7R, 0603; Manufacturer: MuRata; Polarized: N; CompType: Capacitor; Value: 680pF; U/M: EA; Cap_F: 0.00000000068; Tolerance_%: 10; VDC_V: 50; Value2: 50V; TaMin_C: -55; TaMax_C: 125; Cap_Case: 0603; SizeArea_mm2: 1.28; SizeAreaWB_mm2: 4.68; SizeX_mm: 1.6; SizeY_mm: 0.8; SizeZ_mm: 1; AEC Category: Q200; Green_Lifecycle: Active; Green_REACh: Passed
signal-integrity model Cap
simulation model Cap
footprint 0603
footprint 0603M
footprint 0603L
footprint 0603_HV
footprint 0603S
pins: 1, 2

## GRM188R71H682KA01D
designator C?  ValueDisplayed: 6800pF  (hidden comment: GRM188R71H682KA01D)
CAP, CERM, 6800 pF, 50 V,+/- 10%, X7R, 0603; Manufacturer: MuRata; Polarized: N; CompType: Capacitor; Value: 6800pF; U/M: EA; Cap_F: 0.0000000068; Tolerance_%: 10; VDC_V: 50; Value2: 50V; TaMin_C: -55; TaMax_C: 125; Cap_Case: 0603; SizeArea_mm2: 1.28; SizeAreaWB_mm2: 4.68; SizeX_mm: 1.6; SizeY_mm: 0.8; SizeZ_mm: 1; AEC Category: Q200; Green_Lifecycle: Active; Green_REACh: Passed
signal-integrity model Cap
simulation model Cap
footprint 0603
footprint 0603M
footprint 0603L
footprint 0603_HV
footprint 0603S
pins: 1, 2

## GRM188R71H683KA93D
designator C?  ValueDisplayed: 0.068µF  (hidden comment: GRM188R71H683KA93D)
CAP, CERM, 0.068 µF, 50 V,+/- 10%, X7R, 0603; Manufacturer: MuRata; Polarized: N; CompType: Capacitor; Value: 0.068uF; U/M: EA; Cap_F: 0.000000068; Tolerance_%: 10; VDC_V: 50; Value2: 50V; TaMin_C: -55; TaMax_C: 125; Cap_Case: 0603; SizeArea_mm2: 1.28; SizeAreaWB_mm2: 4.68; SizeX_mm: 1.6; SizeY_mm: 0.8; SizeZ_mm: 1; AEC Category: Q200; Green_Lifecycle: Active; Green_REACh: Passed
signal-integrity model Cap
simulation model Cap
footprint 0603
footprint 0603M
footprint 0603L
footprint 0603_HV
footprint 0603S
pins: 1, 2

## GRM188R71H821KA01D
designator C?  ValueDisplayed: 820pF  (hidden comment: GRM188R71H821KA01D)
CAP, CERM, 820 pF, 50 V,+/- 10%, X7R, 0603; Manufacturer: MuRata; Polarized: N; CompType: Capacitor; Value: 820pF; U/M: EA; Cap_F: 0.00000000082; Tolerance_%: 10; VDC_V: 50; Value2: 50V; TaMin_C: -55; TaMax_C: 125; Cap_Case: 0603; SizeArea_mm2: 1.28; SizeAreaWB_mm2: 4.68; SizeX_mm: 1.6; SizeY_mm: 0.8; SizeZ_mm: 1; AEC Category: Q200; Green_Lifecycle: Active; Green_REACh: Passed
signal-integrity model Cap
simulation model Cap
footprint 0603
footprint 0603M
footprint 0603L
footprint 0603_HV
footprint 0603S
pins: 1, 2

## GRM188R71H822KA01D
designator C?  ValueDisplayed: 8200pF  (hidden comment: GRM188R71H822KA01D)
CAP, CERM, 8200 pF, 50 V,+/- 10%, X7R, 0603; Manufacturer: MuRata; Polarized: N; CompType: Capacitor; Value: 8200pF; U/M: EA; Cap_F: 0.0000000082; Tolerance_%: 10; VDC_V: 50; Value2: 50V; TaMin_C: -55; TaMax_C: 125; Cap_Case: 0603; SizeArea_mm2: 1.28; SizeAreaWB_mm2: 4.68; SizeX_mm: 1.6; SizeY_mm: 0.8; SizeZ_mm: 1; AEC Category: Q200; Green_Lifecycle: Active; Green_REACh: Passed
signal-integrity model Cap
simulation model Cap
footprint 0603
footprint 0603M
footprint 0603L
footprint 0603_HV
footprint 0603S
pins: 1, 2

## GRM188R71H823KA93D
designator C?  ValueDisplayed: 0.082µF  (hidden comment: GRM188R71H823KA93D)
CAP, CERM, 0.082 µF, 50 V,+/- 10%, X7R, 0603; Manufacturer: MuRata; Polarized: N; CompType: Capacitor; Value: 0.082uF; U/M: EA; Cap_F: 0.000000082; Tolerance_%: 10; VDC_V: 50; Value2: 50V; TaMin_C: -55; TaMax_C: 125; Cap_Case: 0603; SizeArea_mm2: 1.28; SizeAreaWB_mm2: 4.68; SizeX_mm: 1.6; SizeY_mm: 0.8; SizeZ_mm: 1; AEC Category: Q200; Green_Lifecycle: Active; Green_REACh: Passed
signal-integrity model Cap
simulation model Cap
footprint 0603
footprint 0603M
footprint 0603L
footprint 0603_HV
footprint 0603S
pins: 1, 2

## GRM188R72A102KA01D
designator C?  ValueDisplayed: 1000pF  (hidden comment: GRM188R72A102KA01D)
CAP, CERM, 1000 pF, 100 V,+/- 10%, X7R, 0603; Manufacturer: MuRata; Polarized: N; CompType: Capacitor; Value: 1000pF; U/M: EA; Cap_F: 0.000000001; Tolerance_%: 10; VDC_V: 100; Value2: 100V; TaMin_C: -55; TaMax_C: 125; Cap_Case: 0603; SizeArea_mm2: 1.28; SizeAreaWB_mm2: 4.68; SizeX_mm: 1.6; SizeY_mm: 0.8; SizeZ_mm: 1; AEC Category: Q200; Green_Lifecycle: Active; Green_REACh: Passed
signal-integrity model Cap
simulation model Cap
footprint 0603
footprint 0603M
footprint 0603L
footprint 0603_HV
footprint 0603S
pins: 1, 2

## GRM188R72A103KA01D
designator C?  ValueDisplayed: 0.01µF  (hidden comment: GRM188R72A103KA01D)
CAP, CERM, 0.01 µF, 100 V,+/- 10%, X7R, 0603; Manufacturer: MuRata; Polarized: N; CompType: Capacitor; Value: 0.01uF; U/M: EA; Cap_F: 0.00000001; Tolerance_%: 10; VDC_V: 100; Value2: 100V; TaMin_C: -55; TaMax_C: 125; Cap_Case: 0603; SizeArea_mm2: 1.28; SizeAreaWB_mm2: 4.68; SizeX_mm: 1.6; SizeY_mm: 0.8; SizeZ_mm: 1; AEC Category: Q200; Green_Lifecycle: Active; Green_REACh: Passed
signal-integrity model Cap
simulation model Cap
footprint 0603
footprint 0603M
footprint 0603L
footprint 0603_HV
footprint 0603S
pins: 1, 2

## GRM188R72A104KA35D
designator C?  ValueDisplayed: 0.1µF  (hidden comment: GRM188R72A104KA35D)
CAP, CERM, 0.1 µF, 100 V,+/- 10%, X7R, 0603; Manufacturer: MuRata; Polarized: N; CompType: Capacitor; Value: 0.1uF; U/M: EA; Cap_F: 0.0000001; Tolerance_%: 10; VDC_V: 100; Value2: 100V; TaMin_C: -55; TaMax_C: 125; Cap_Case: 0603; SizeArea_mm2: 1.28; SizeAreaWB_mm2: 4.68; SizeX_mm: 1.6; SizeY_mm: 0.8; SizeZ_mm: 1; AEC Category: Q200; Green_Lifecycle: Active; Green_REACh: Passed
signal-integrity model Cap
simulation model Cap
footprint 0603
footprint 0603M
footprint 0603L
footprint 0603_HV
footprint 0603S
pins: 1, 2

## GRM188R72A104KA35J
designator C?  ValueDisplayed: 0.1µF  (hidden comment: GRM188R72A104KA35J)
CAP, CERM, 0.1 µF, 100 V,+/- 10%, X7R, 0603; Manufacturer: MuRata; Polarized: N; CompType: Capacitor; Value: 0.1uF; U/M: EA; Cap_F: 0.0000001; Tolerance_%: 10; VDC_V: 100; Value2: 100V; TaMin_C: -55; TaMax_C: 125; Cap_Case: 0603; SizeArea_mm2: 1.28; SizeAreaWB_mm2: 4.68; SizeX_mm: 1.6; SizeY_mm: 0.8; SizeZ_mm: 1; AEC Category: Q200; Green_Lifecycle: Active; Green_REACh: Passed
signal-integrity model Cap
simulation model Cap
footprint 0603
footprint 0603M
footprint 0603L
footprint 0603_HV
footprint 0603S
pins: 1, 2

## GRM188R72A122KA01D
designator C?  ValueDisplayed: 1200pF  (hidden comment: GRM188R72A122KA01D)
CAP, CERM, 1200 pF, 100 V,+/- 10%, X7R, 0603; Manufacturer: MuRata; Polarized: N; CompType: Capacitor; Value: 1200pF; U/M: EA; Cap_F: 0.0000000012; Tolerance_%: 10; VDC_V: 100; Value2: 100V; TaMin_C: -55; TaMax_C: 125; Cap_Case: 0603; SizeArea_mm2: 1.28; SizeAreaWB_mm2: 4.68; SizeX_mm: 1.6; SizeY_mm: 0.8; SizeZ_mm: 1; AEC Category: Q200
signal-integrity model Cap
simulation model Cap
footprint 0603
footprint 0603M
footprint 0603L
footprint 0603_HV
footprint 0603S
pins: 1, 2

## GRM188R72A152KA01D
designator C?  ValueDisplayed: 1500pF  (hidden comment: GRM188R72A152KA01D)
CAP, CERM, 1500 pF, 100 V,+/- 10%, X7R, 0603; Manufacturer: MuRata; Polarized: N; CompType: Capacitor; Value: 1500pF; U/M: EA; Cap_F: 0.0000000015; Tolerance_%: 10; VDC_V: 100; Value2: 100V; TaMin_C: -55; TaMax_C: 125; Cap_Case: 0603; SizeArea_mm2: 1.28; SizeAreaWB_mm2: 4.68; SizeX_mm: 1.6; SizeY_mm: 0.8; SizeZ_mm: 1; AEC Category: Q200
signal-integrity model Cap
simulation model Cap
footprint 0603
footprint 0603M
footprint 0603L
footprint 0603_HV
footprint 0603S
pins: 1, 2

## GRM188R72A182KA01D
designator C?  ValueDisplayed: 1800pF  (hidden comment: GRM188R72A182KA01D)
CAP, CERM, 1800 pF, 100 V,+/- 10%, X7R, 0603; Manufacturer: MuRata; Polarized: N; CompType: Capacitor; Value: 1800pF; U/M: EA; Cap_F: 0.0000000018; Tolerance_%: 10; VDC_V: 100; Value2: 100V; TaMin_C: -55; TaMax_C: 125; Cap_Case: 0603; SizeArea_mm2: 1.28; SizeAreaWB_mm2: 4.68; SizeX_mm: 1.6; SizeY_mm: 0.8; SizeZ_mm: 1; AEC Category: Q200
signal-integrity model Cap
simulation model Cap
footprint 0603
footprint 0603M
footprint 0603L
footprint 0603_HV
footprint 0603S
pins: 1, 2

## GRM188R72A221KA01D
designator C?  ValueDisplayed: 220pF  (hidden comment: GRM188R72A221KA01D)
CAP, CERM, 220 pF, 100 V,+/- 10%, X7R, 0603; Manufacturer: MuRata; Polarized: N; CompType: Capacitor; Value: 220pF; U/M: EA; Cap_F: 0.00000000022; Tolerance_%: 10; VDC_V: 100; Value2: 100V; TaMin_C: -55; TaMax_C: 125; Cap_Case: 0603; SizeArea_mm2: 1.28; SizeAreaWB_mm2: 4.68; SizeX_mm: 1.6; SizeY_mm: 0.8; SizeZ_mm: 1; AEC Category: Q200
signal-integrity model Cap
simulation model Cap
footprint 0603
footprint 0603M
footprint 0603L
footprint 0603_HV
footprint 0603S
pins: 1, 2

## GRM188R72A222KA01D
designator C?  ValueDisplayed: 2200pF  (hidden comment: GRM188R72A222KA01D)
CAP, CERM, 2200 pF, 100 V,+/- 10%, X7R, 0603; Manufacturer: MuRata; Polarized: N; CompType: Capacitor; Value: 2200pF; U/M: EA; Cap_F: 0.0000000022; Tolerance_%: 10; VDC_V: 100; Value2: 100V; TaMin_C: -55; TaMax_C: 125; Cap_Case: 0603; SizeArea_mm2: 1.28; SizeAreaWB_mm2: 4.68; SizeX_mm: 1.6; SizeY_mm: 0.8; SizeZ_mm: 1; AEC Category: Q200
signal-integrity model Cap
simulation model Cap
footprint 0603
footprint 0603M
footprint 0603L
footprint 0603_HV
footprint 0603S
pins: 1, 2

## GRM188R72A271KA01D
designator C?  ValueDisplayed: 270pF  (hidden comment: GRM188R72A271KA01D)
CAP, CERM, 270 pF, 100 V,+/- 10%, X7R, 0603; Manufacturer: MuRata; Polarized: N; CompType: Capacitor; Value: 270pF; U/M: EA; Cap_F: 0.00000000027; Tolerance_%: 10; VDC_V: 100; Value2: 100V; TaMin_C: -55; TaMax_C: 125; Cap_Case: 0603; SizeArea_mm2: 1.28; SizeAreaWB_mm2: 4.68; SizeX_mm: 1.6; SizeY_mm: 0.8; SizeZ_mm: 1; AEC Category: Q200
signal-integrity model Cap
simulation model Cap
footprint 0603
footprint 0603M
footprint 0603L
footprint 0603_HV
footprint 0603S
pins: 1, 2

## GRM188R72A272KA01D
designator C?  ValueDisplayed: 2700pF  (hidden comment: GRM188R72A272KA01D)
CAP, CERM, 2700 pF, 100 V,+/- 10%, X7R, 0603; Manufacturer: MuRata; Polarized: N; CompType: Capacitor; Value: 2700pF; U/M: EA; Cap_F: 0.0000000027; Tolerance_%: 10; VDC_V: 100; Value2: 100V; TaMin_C: -55; TaMax_C: 125; Cap_Case: 0603; SizeArea_mm2: 1.28; SizeAreaWB_mm2: 4.68; SizeX_mm: 1.6; SizeY_mm: 0.8; SizeZ_mm: 1; AEC Category: Q200
signal-integrity model Cap
simulation model Cap
footprint 0603
footprint 0603M
footprint 0603L
footprint 0603_HV
footprint 0603S
pins: 1, 2

## GRM188R72A331KA01D
designator C?  ValueDisplayed: 330pF  (hidden comment: GRM188R72A331KA01D)
CAP, CERM, 330 pF, 100 V,+/- 10%, X7R, 0603; Manufacturer: MuRata; Polarized: N; CompType: Capacitor; Value: 330pF; U/M: EA; Cap_F: 0.00000000033; Tolerance_%: 10; VDC_V: 100; Value2: 100V; TaMin_C: -55; TaMax_C: 125; Cap_Case: 0603; SizeArea_mm2: 1.28; SizeAreaWB_mm2: 4.68; SizeX_mm: 1.6; SizeY_mm: 0.8; SizeZ_mm: 1; AEC Category: Q200
signal-integrity model Cap
simulation model Cap
footprint 0603
footprint 0603M
footprint 0603L
footprint 0603_HV
footprint 0603S
pins: 1, 2

## GRM188R72A332KA01D
designator C?  ValueDisplayed: 3300pF  (hidden comment: GRM188R72A332KA01D)
CAP, CERM, 3300 pF, 100 V,+/- 10%, X7R, 0603; Manufacturer: MuRata; Polarized: N; CompType: Capacitor; Value: 3300pF; U/M: EA; Cap_F: 0.0000000033; Tolerance_%: 10; VDC_V: 100; Value2: 100V; TaMin_C: -55; TaMax_C: 125; Cap_Case: 0603; SizeArea_mm2: 1.28; SizeAreaWB_mm2: 4.68; SizeX_mm: 1.6; SizeY_mm: 0.8; SizeZ_mm: 1; AEC Category: Q200; Green_Lifecycle: Active; Green_REACh: Passed
signal-integrity model Cap
simulation model Cap
footprint 0603
footprint 0603M
footprint 0603L
footprint 0603_HV
footprint 0603S
pins: 1, 2

## GRM188R72A391KA01D
designator C?  ValueDisplayed: 390pF  (hidden comment: GRM188R72A391KA01D)
CAP, CERM, 390 pF, 100 V,+/- 10%, X7R, 0603; Manufacturer: MuRata; Polarized: N; CompType: Capacitor; Value: 390pF; U/M: EA; Cap_F: 0.00000000039; Tolerance_%: 10; VDC_V: 100; Value2: 100V; TaMin_C: -55; TaMax_C: 125; Cap_Case: 0603; SizeArea_mm2: 1.28; SizeAreaWB_mm2: 4.68; SizeX_mm: 1.6; SizeY_mm: 0.8; SizeZ_mm: 1; AEC Category: Q200
signal-integrity model Cap
simulation model Cap
footprint 0603
footprint 0603M
footprint 0603L
footprint 0603_HV
footprint 0603S
pins: 1, 2

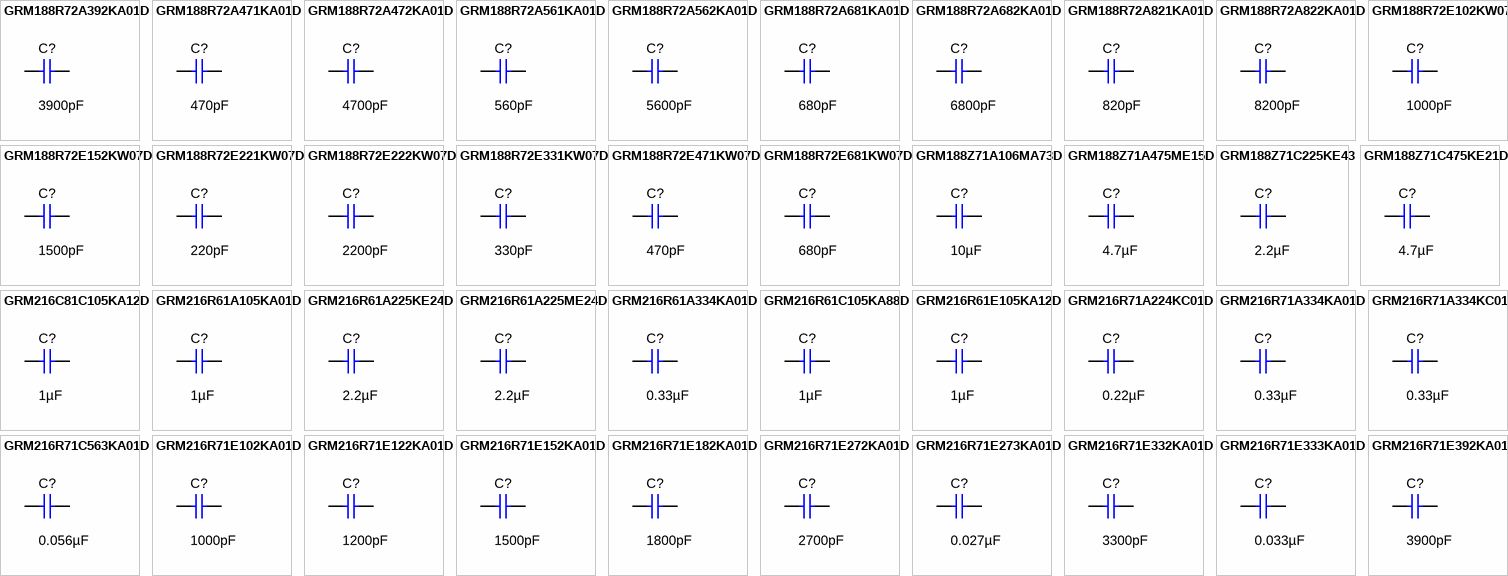
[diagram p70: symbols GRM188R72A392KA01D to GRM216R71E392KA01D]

## GRM188R72A392KA01D
designator C?  ValueDisplayed: 3900pF  (hidden comment: GRM188R72A392KA01D)
CAP, CERM, 3900 pF, 100 V,+/- 10%, X7R, 0603; Manufacturer: MuRata; Polarized: N; CompType: Capacitor; Value: 3900pF; U/M: EA; Cap_F: 0.0000000039; Tolerance_%: 10; VDC_V: 100; Value2: 100V; TaMin_C: -55; TaMax_C: 125; Cap_Case: 0603; SizeArea_mm2: 1.28; SizeAreaWB_mm2: 4.68; SizeX_mm: 1.6; SizeY_mm: 0.8; SizeZ_mm: 1; AEC Category: Q200
signal-integrity model Cap
simulation model Cap
footprint 0603
footprint 0603M
footprint 0603L
footprint 0603_HV
footprint 0603S
pins: 1, 2

## GRM188R72A471KA01D
designator C?  ValueDisplayed: 470pF  (hidden comment: GRM188R72A471KA01D)
CAP, CERM, 470 pF, 100 V,+/- 10%, X7R, 0603; Manufacturer: MuRata; Polarized: N; CompType: Capacitor; Value: 470pF; U/M: EA; Cap_F: 0.00000000047; Tolerance_%: 10; VDC_V: 100; Value2: 100V; TaMin_C: -55; TaMax_C: 125; Cap_Case: 0603; SizeArea_mm2: 1.28; SizeAreaWB_mm2: 4.68; SizeX_mm: 1.6; SizeY_mm: 0.8; SizeZ_mm: 1; AEC Category: Q200
signal-integrity model Cap
simulation model Cap
footprint 0603
footprint 0603M
footprint 0603L
footprint 0603_HV
footprint 0603S
pins: 1, 2

## GRM188R72A472KA01D
designator C?  ValueDisplayed: 4700pF  (hidden comment: GRM188R72A472KA01D)
CAP, CERM, 4700 pF, 100 V,+/- 10%, X7R, 0603; Manufacturer: MuRata; Polarized: N; CompType: Capacitor; Value: 4700pF; U/M: EA; Cap_F: 0.0000000047; Tolerance_%: 10; VDC_V: 100; Value2: 100V; TaMin_C: -55; TaMax_C: 125; Cap_Case: 0603; SizeArea_mm2: 1.28; SizeAreaWB_mm2: 4.68; SizeX_mm: 1.6; SizeY_mm: 0.8; SizeZ_mm: 1; AEC Category: Q200
signal-integrity model Cap
simulation model Cap
footprint 0603
footprint 0603M
footprint 0603L
footprint 0603_HV
footprint 0603S
pins: 1, 2

## GRM188R72A561KA01D
designator C?  ValueDisplayed: 560pF  (hidden comment: GRM188R72A561KA01D)
CAP, CERM, 560 pF, 100 V,+/- 10%, X7R, 0603; Manufacturer: MuRata; Polarized: N; CompType: Capacitor; Value: 560pF; U/M: EA; Cap_F: 0.00000000056; Tolerance_%: 10; VDC_V: 100; Value2: 100V; TaMin_C: -55; TaMax_C: 125; Cap_Case: 0603; SizeArea_mm2: 1.28; SizeAreaWB_mm2: 4.68; SizeX_mm: 1.6; SizeY_mm: 0.8; SizeZ_mm: 1; AEC Category: Q200
signal-integrity model Cap
simulation model Cap
footprint 0603
footprint 0603M
footprint 0603L
footprint 0603_HV
footprint 0603S
pins: 1, 2

## GRM188R72A562KA01D
designator C?  ValueDisplayed: 5600pF  (hidden comment: GRM188R72A562KA01D)
CAP, CERM, 5600 pF, 100 V,+/- 10%, X7R, 0603; Manufacturer: MuRata; Polarized: N; CompType: Capacitor; Value: 5600pF; U/M: EA; Cap_F: 0.0000000056; Tolerance_%: 10; VDC_V: 100; Value2: 100V; TaMin_C: -55; TaMax_C: 125; Cap_Case: 0603; SizeArea_mm2: 1.28; SizeAreaWB_mm2: 4.68; SizeX_mm: 1.6; SizeY_mm: 0.8; SizeZ_mm: 1; AEC Category: Q200
signal-integrity model Cap
simulation model Cap
footprint 0603
footprint 0603M
footprint 0603L
footprint 0603_HV
footprint 0603S
pins: 1, 2

## GRM188R72A681KA01D
designator C?  ValueDisplayed: 680pF  (hidden comment: GRM188R72A681KA01D)
CAP, CERM, 680 pF, 100 V,+/- 10%, X7R, 0603; Manufacturer: MuRata; Polarized: N; CompType: Capacitor; Value: 680pF; U/M: EA; Cap_F: 0.00000000068; Tolerance_%: 10; VDC_V: 100; Value2: 100V; TaMin_C: -55; TaMax_C: 125; Cap_Case: 0603; SizeArea_mm2: 1.28; SizeAreaWB_mm2: 4.68; SizeX_mm: 1.6; SizeY_mm: 0.8; SizeZ_mm: 1; AEC Category: Q200
signal-integrity model Cap
simulation model Cap
footprint 0603
footprint 0603M
footprint 0603L
footprint 0603_HV
footprint 0603S
pins: 1, 2

## GRM188R72A682KA01D
designator C?  ValueDisplayed: 6800pF  (hidden comment: GRM188R72A682KA01D)
CAP, CERM, 6800 pF, 100 V,+/- 10%, X7R, 0603; Manufacturer: MuRata; Polarized: N; CompType: Capacitor; Value: 6800pF; U/M: EA; Cap_F: 0.0000000068; Tolerance_%: 10; VDC_V: 100; Value2: 100V; TaMin_C: -55; TaMax_C: 125; Cap_Case: 0603; SizeArea_mm2: 1.28; SizeAreaWB_mm2: 4.68; SizeX_mm: 1.6; SizeY_mm: 0.8; SizeZ_mm: 1; AEC Category: Q200
signal-integrity model Cap
simulation model Cap
footprint 0603
footprint 0603M
footprint 0603L
footprint 0603_HV
footprint 0603S
pins: 1, 2

## GRM188R72A821KA01D
designator C?  ValueDisplayed: 820pF  (hidden comment: GRM188R72A821KA01D)
CAP, CERM, 820 pF, 100 V,+/- 10%, X7R, 0603; Manufacturer: MuRata; Polarized: N; CompType: Capacitor; Value: 820pF; U/M: EA; Cap_F: 0.00000000082; Tolerance_%: 10; VDC_V: 100; Value2: 100V; TaMin_C: -55; TaMax_C: 125; Cap_Case: 0603; SizeArea_mm2: 1.28; SizeAreaWB_mm2: 4.68; SizeX_mm: 1.6; SizeY_mm: 0.8; SizeZ_mm: 1; AEC Category: Q200; Green_Lifecycle: Active; Green_REACh: Passed
signal-integrity model Cap
simulation model Cap
footprint 0603
footprint 0603M
footprint 0603L
footprint 0603_HV
footprint 0603S
pins: 1, 2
